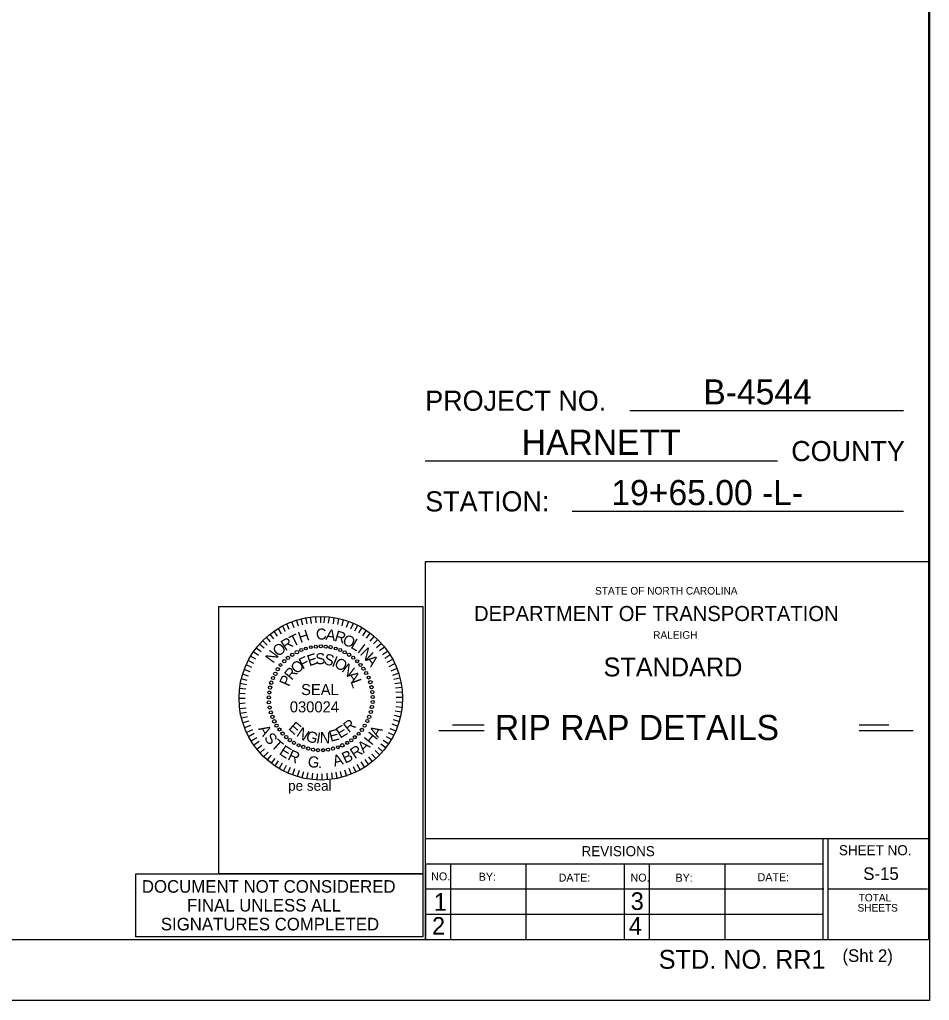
# Model space of a CAD drawing. Extents: x 0 to 265, y -200 to 22.
# Drawn here: x 192.2 to 264.5, y -176 to -98.1 of the extents above; entities that cross this region are included whole.
import ezdxf

# ---------------------------------------------------------------- set-up
doc = ezdxf.new("R2010")
doc.units = 0
for name, color, linetype in [('Peseal', 7, 'Continuous'), ('Plan Sheet', 7, 'Continuous'), ('Plan Sheet CELL', 7, 'Continuous'), ('Plot Shape', 7, 'Continuous'), ('Sheet Sticker Exception Certification CELL', 7, 'Continuous'), ('Text', 7, 'Continuous'), ('Title Text', 7, 'Continuous'), ('User Information Notes', 7, 'Continuous'), ('User Information Notes CELL', 7, 'Continuous')]:
    doc.layers.add(name, color=color, linetype=linetype)

msp = doc.modelspace()

# ---------------------------------------------------------------- linework, layer by layer
at = {"layer": 'Peseal'}
for p, q in [((214.699, -146.176), (214.574, -145.676)), ((215.043, -146.082), (214.949, -145.582)), ((215.387, -146.051), (215.324, -145.551)), ((215.762, -145.988), (215.73, -145.488)), ((216.137, -145.988), (216.137, -145.488)), ((216.418, -145.988), (216.449, -145.488)), ((216.762, -146.019), (216.824, -145.519)), ((217.137, -146.082), (217.199, -145.582)), ((217.48, -146.144), (217.574, -145.644)), ((217.824, -146.238), (217.949, -145.738)), ((213.012, -146.863), (212.762, -146.426)), ((213.324, -146.676), (213.105, -146.238)), ((213.637, -146.519), (213.449, -146.082)), ((214.012, -146.394), (213.824, -145.926)), ((214.355, -146.269), (214.199, -145.769)), ((218.168, -146.332), (218.355, -145.863)), ((218.512, -146.488), (218.73, -146.019)), ((218.855, -146.644), (219.074, -146.176)), ((219.168, -146.801), (219.418, -146.363)), ((212.137, -147.519), (211.824, -147.144)), ((212.418, -147.269), (212.105, -146.894)), ((212.699, -147.051), (212.418, -146.644)), ((219.481, -147.019), (219.762, -146.582)), ((219.762, -147.207), (220.074, -146.832)), ((220.074, -147.457), (220.387, -147.082)), ((211.387, -148.301), (211.012, -148.019)), ((211.637, -148.019), (211.262, -147.707)), ((211.887, -147.769), (211.512, -147.394)), ((220.324, -147.676), (220.668, -147.332)), ((220.574, -147.957), (220.949, -147.613)), ((220.793, -148.207), (221.199, -147.894)), ((210.98, -148.895), (210.543, -148.644)), ((211.199, -148.582), (210.762, -148.301)), ((221.043, -148.519), (221.449, -148.238)), ((221.231, -148.801), (221.637, -148.551)), ((210.668, -149.551), (210.199, -149.332)), ((210.824, -149.238), (210.355, -148.988)), ((221.418, -149.113), (221.856, -148.895)), ((221.574, -149.457), (222.012, -149.238)), ((221.731, -149.801), (222.199, -149.613)), ((210.387, -150.238), (209.918, -150.082)), ((210.512, -149.895), (210.043, -149.707)), ((221.856, -150.145), (222.324, -149.988)), ((221.949, -150.488), (222.418, -150.363)), ((210.23, -150.926), (209.73, -150.832)), ((210.293, -150.582), (209.824, -150.457)), ((222.012, -150.832), (222.512, -150.738)), ((222.074, -151.176), (222.574, -151.113)), ((210.137, -151.645), (209.637, -151.613)), ((210.168, -151.27), (209.699, -151.207)), ((222.106, -151.52), (222.606, -151.488)), ((222.137, -151.895), (222.637, -151.895)), ((210.137, -152.02), (209.637, -152.02)), ((210.137, -152.395), (209.637, -152.426)), ((222.106, -152.645), (222.606, -152.707)), ((222.137, -152.27), (222.637, -152.301)), ((210.199, -152.77), (209.699, -152.832)), ((210.23, -153.113), (209.762, -153.207)), ((210.324, -153.457), (209.824, -153.582)), ((221.981, -153.332), (222.481, -153.457)), ((222.043, -152.988), (222.543, -153.082)), ((210.418, -153.801), (209.949, -153.957)), ((210.543, -154.145), (210.074, -154.332)), ((221.793, -154.02), (222.262, -154.207)), ((221.887, -153.676), (222.387, -153.832)), ((210.699, -154.488), (210.23, -154.707)), ((210.855, -154.801), (210.387, -155.051)), ((221.324, -155.02), (221.762, -155.27)), ((221.481, -154.707), (221.949, -154.926)), ((221.637, -154.395), (222.106, -154.582)), ((211.043, -155.145), (210.605, -155.395)), ((211.23, -155.426), (210.824, -155.707)), ((211.449, -155.738), (211.043, -156.051)), ((220.918, -155.613), (221.324, -155.926)), ((221.106, -155.332), (221.543, -155.613)), ((211.668, -156.02), (211.324, -156.332)), ((211.949, -156.27), (211.574, -156.645)), ((212.199, -156.52), (211.887, -156.895)), ((219.918, -156.645), (220.231, -157.051)), ((220.199, -156.426), (220.512, -156.77)), ((220.449, -156.145), (220.824, -156.52)), ((220.699, -155.895), (221.074, -156.238)), ((212.48, -156.77), (212.199, -157.145)), ((212.762, -156.957), (212.48, -157.363)), ((213.074, -157.145), (212.824, -157.582)), ((213.387, -157.332), (213.168, -157.77)), ((218.699, -157.426), (218.918, -157.863)), ((219.012, -157.238), (219.262, -157.707)), ((219.324, -157.051), (219.606, -157.488)), ((219.637, -156.863), (219.918, -157.27)), ((213.699, -157.488), (213.512, -157.926)), ((214.043, -157.613), (213.887, -158.082)), ((214.418, -157.738), (214.262, -158.207)), ((214.762, -157.832), (214.637, -158.301)), ((215.105, -157.895), (215.012, -158.395)), ((215.48, -157.957), (215.418, -158.457)), ((215.855, -157.988), (215.824, -158.488)), ((216.23, -157.988), (216.23, -158.488)), ((216.605, -157.957), (216.637, -158.457)), ((216.98, -157.926), (217.043, -158.426)), ((217.324, -157.863), (217.418, -158.363)), ((217.668, -157.801), (217.793, -158.27)), ((218.012, -157.676), (218.168, -158.176)), ((218.355, -157.551), (218.543, -158.02))]:
    msp.add_line(p, q, dxfattribs=at)
for centre, radius in [((214.59, -148.16), 0.119), ((214.949, -148.035), 0.114), ((215.34, -147.941), 0.11), ((215.746, -147.894), 0.126), ((216.137, -147.863), 0.125), ((216.527, -147.894), 0.126), ((216.918, -147.926), 0.129), ((217.324, -148.035), 0.114), ((217.684, -148.16), 0.119), ((213.527, -148.785), 0.134), ((213.871, -148.535), 0.134), ((214.23, -148.332), 0.14), ((218.043, -148.348), 0.126), ((218.387, -148.535), 0.126), ((218.715, -148.769), 0.122), ((212.715, -149.691), 0.134), ((212.934, -149.348), 0.11), ((213.23, -149.051), 0.133), ((219.027, -149.051), 0.122), ((219.293, -149.348), 0.122), ((219.527, -149.644), 0.126), ((212.34, -150.379), 0.119), ((212.527, -150.051), 0.144), ((219.746, -149.988), 0.126), ((219.934, -150.348), 0.119), ((212.105, -151.145), 0.129), ((212.199, -150.754), 0.134), ((220.074, -150.723), 0.134), ((220.168, -151.113), 0.129), ((212.012, -151.926), 0.125), ((212.043, -151.535), 0.126), ((220.231, -151.504), 0.126), ((220.262, -151.895), 0.125), ((212.012, -152.316), 0.126), ((212.074, -152.723), 0.126), ((220.199, -152.691), 0.126), ((220.262, -152.285), 0.126), ((212.168, -153.113), 0.129), ((212.293, -153.473), 0.134), ((219.981, -153.473), 0.134), ((220.106, -153.082), 0.129), ((212.449, -153.832), 0.14), ((212.621, -154.176), 0.126), ((219.621, -154.176), 0.126), ((219.84, -153.801), 0.126), ((212.855, -154.473), 0.122), ((213.105, -154.801), 0.133), ((213.387, -155.082), 0.133), ((218.84, -155.082), 0.122), ((219.137, -154.816), 0.122), ((219.402, -154.504), 0.134), ((213.684, -155.316), 0.134), ((214.012, -155.535), 0.126), ((214.371, -155.723), 0.119), ((214.746, -155.863), 0.134), ((215.137, -155.988), 0.129), ((217.105, -155.988), 0.129), ((217.496, -155.879), 0.119), ((217.855, -155.738), 0.14), ((218.23, -155.535), 0.126), ((218.559, -155.332), 0.122), ((215.527, -156.082), 0.126), ((215.918, -156.113), 0.125), ((216.324, -156.113), 0.125), ((216.715, -156.082), 0.126)]:
    msp.add_circle(centre, radius, dxfattribs=at)
at = {"layer": 'Plan Sheet'}
for p, q in [((264.435, -3.151), (264.435, -171.151)), ((8.432, -171.151), (264.435, -171.151)), ((264.505, -176), (264.505, -176))]:
    msp.add_line(p, q, dxfattribs=at)
at = {"layer": 'Plan Sheet CELL'}
for p, q in [((262.437, -129.149), (240.7, -129.149)), ((252.436, -133.15), (224.437, -133.15)), ((262.437, -137.147), (236.119, -137.147)), ((264.435, -141.148), (224.437, -141.148)), ((224.437, -141.148), (224.437, -171.151)), ((224.437, -163.148), (264.435, -163.148)), ((256.038, -163.148), (256.038, -171.151)), ((256.438, -163.148), (256.438, -171.151)), ((224.437, -165.146), (256.053, -165.146)), ((224.461, -165.146), (224.461, -171.151)), ((226.435, -165.146), (226.435, -171.151)), ((232.434, -165.181), (232.434, -171.181)), ((240.242, -165.146), (240.242, -171.201)), ((242.246, -165.146), (242.246, -171.156)), ((248.245, -165.146), (248.245, -171.156)), ((224.437, -167.149), (256.118, -167.149)), ((256.438, -167.149), (264.365, -167.149)), ((224.437, -169.148), (256.053, -169.148))]:
    msp.add_line(p, q, dxfattribs=at)
at = {"layer": 'Plot Shape'}
msp.add_lwpolyline([(0, 0), (264.505, 0), (264.505, -176), (0, -176)], close=True, dxfattribs=at)
at = {"layer": 'Sheet Sticker Exception Certification CELL'}
msp.add_lwpolyline([(201.448, -165.935), (224.237, -165.935), (224.237, -170.951), (201.448, -170.951)], close=True, dxfattribs=at)
at = {"layer": 'Text'}
for p, q in [((226.601, -154.094), (229.123, -154.094)), ((258.936, -154.094), (261.29, -154.094)), ((225.511, -154.543), (229.123, -154.543)), ((258.936, -154.543), (263.213, -154.543))]:
    msp.add_line(p, q, dxfattribs=at)
at = {"layer": 'User Information Notes'}
msp.add_line((216.137, -151.988), (216.137, -151.988), dxfattribs=at)
at = {"layer": 'User Information Notes CELL'}
msp.add_line((216.137, -151.988), (216.137, -151.988), dxfattribs=at)
msp.add_lwpolyline([(208.037, -144.688), (224.237, -144.688), (224.237, -165.935), (208.037, -165.935)], close=True, dxfattribs=at)
msp.add_circle((216.137, -151.988), 6.5, dxfattribs=at)

# ---------------------------------------------------------------- texts
at = {"layer": 'Peseal'}
for s, height, rotation, p in [('C', 0.875, 4.86248, (215.793, -147.363)), ('R', 0.875, 32.96988, (213.324, -148.269)), ('T', 0.875, 25.94303, (213.918, -147.926)), ('H', 0.875, 18.91618, (214.512, -147.613)), ('A', 0.875, 350.80878, (216.48, -147.332)), ('R', 0.875, 343.78193, (217.168, -147.426)), ('O', 0.875, 336.75507, (217.793, -147.676)), ('L', 0.875, 329.72823, (218.449, -147.957)), ('O', 0.875, 39.99672, (212.762, -148.738)), ('I', 0.875, 322.70138, (218.98, -148.301)), ('N', 0.875, 315.67453, (219.199, -148.488)), ('N', 0.875, 54.05043, (212.355, -149.27)), ('F', 0.875, 26.4777, (214.668, -149.707)), ('E', 0.875, 18.44476, (215.23, -149.457)), ('S', 0.875, 2.37887, (215.73, -149.301)), ('S', 0.875, 346.31297, (216.324, -149.27)), ('I', 0.875, 338.28003, (216.949, -149.426)), ('O', 0.875, 330.24709, (217.137, -149.457)), ('A', 0.875, 308.64767, (219.637, -148.957)), ('R', 0.875, 50.57654, (213.824, -150.613)), ('O', 0.875, 42.54359, (214.23, -150.113)), ('N', 0.875, 322.21414, (217.73, -149.832)), ('P', 0.875, 66.64243, (213.605, -151.113)), ('A', 0.875, 306.14825, (218.168, -150.207)), ('L', 0.875, 290.08236, (218.48, -150.645)), ('A', 0.887, 300.39928, (211.139, -154.414)), ('E', 0.875, 318.51794, (213.512, -154.426)), ('N', 0.875, 326.53612, (214.137, -154.957)), ('E', 0.875, 30.68151, (217.668, -155.207)), ('R', 0.875, 38.69968, (218.355, -154.77)), ('S', 0.887, 309.43491, (211.582, -155.169)), ('G', 0.875, 342.57247, (214.887, -155.363)), ('I', 0.875, 350.59064, (215.73, -155.551)), ('N', 0.875, 358.60881, (216.043, -155.551)), ('E', 0.875, 14.64516, (216.918, -155.457)), ('H', 0.887, 51.35972, (220.19, -155.788)), ('A', 0.887, 59.60072, (220.693, -155.167)), ('T', 0.887, 318.10965, (212.114, -155.82)), ('E', 0.887, 327.14527, (212.765, -156.404)), ('R', 0.887, 33.57762, (218.836, -156.844)), ('A', 0.887, 42.32409, (219.543, -156.377)), ('R', 0.888, 335.458, (213.439, -156.845)), ('G', 0.887, 353.38579, (215.065, -157.44)), ('A', 0.887, 15.79553, (217.224, -157.436)), ('B', 0.887, 24.83116, (218.066, -157.198)), ('.', 0.887, 2.13226, (215.906, -157.539))]:
    msp.add_text(s, height=height, rotation=rotation, dxfattribs=at).set_placement(p)
for s, p in [('SEAL', (214.574, -151.738)), ('030024', (213.677, -153.113))]:
    msp.add_text(s, height=0.8751, dxfattribs=at).set_placement(p)
at = {"layer": 'Plan Sheet CELL'}
for s, height, p in [('PROJECT NO.', 1.6, (224.437, -129.149)), ('COUNTY', 1.6, (253.526, -133.15)), ('STATION:', 1.6, (224.437, -137.147)), ('STATE OF NORTH CAROLINA', 0.59996, (237.935, -143.75)), ('DEPARTMENT OF TRANSPORTATION', 1.19996, (228.316, -145.859)), ('RALEIGH', 0.6, (242.554, -147.262)), ('SHEET NO.', 0.8, (257.318, -164.467)), ('REVISIONS', 0.8, (236.857, -164.542)), ('NO.', 0.6375, (224.911, -166.465)), ('BY:', 0.6375, (228.688, -166.495)), ('DATE:', 0.6375, (235.042, -166.565)), ('NO.', 0.6375, (240.752, -166.565)), ('BY:', 0.6375, (244.324, -166.57)), ('DATE:', 0.6375, (250.848, -166.53)), ('1', 1.4, (225.121, -168.878)), ('3', 1.4, (240.767, -168.813)), ('TOTAL', 0.6, (258.886, -168.134)), ('SHEETS', 0.6, (258.794, -168.943)), ('2', 1.4, (224.976, -170.781)), ('4', 1.4, (240.617, -170.781))]:
    msp.add_text(s, height=height, dxfattribs=at).set_placement(p)
at = {"layer": 'Sheet Sticker Exception Certification CELL'}
for s, p in [('DOCUMENT NOT CONSIDERED', (201.917, -167.444)), ('FINAL UNLESS ALL', (205.503, -168.941)), ('SIGNATURES COMPLETED', (203.425, -170.437))]:
    msp.add_text(s, height=0.99777, dxfattribs=at).set_placement(p)
at = {"layer": 'Text'}
for s, height, p in [('STANDARD', 1.5, (238.61, -150.256)), ('RIP RAP DETAILS', 2, (229.969, -155.315)), ('S-15', 1, (259.248, -166.431)), ('STD. NO. RR1', 1.5, (242.995, -173.488)), ('(Sht 2)', 0.9977, (257.6, -172.941))]:
    msp.add_text(s, height=height, dxfattribs=at).set_placement(p)
at = {"layer": 'Title Text'}
for s, p in [('B-4544', (246.537, -128.649)), ('HARNETT', (232.106, -132.65)), ('19+65.00 -L-', (239.232, -136.647))]:
    msp.add_text(s, height=2, dxfattribs=at).set_placement(p)
at = {"layer": 'User Information Notes CELL'}
msp.add_text('pe seal', height=0.8, dxfattribs=at).set_placement((213.544, -159.342))

doc.saveas('drawing.dxf')
